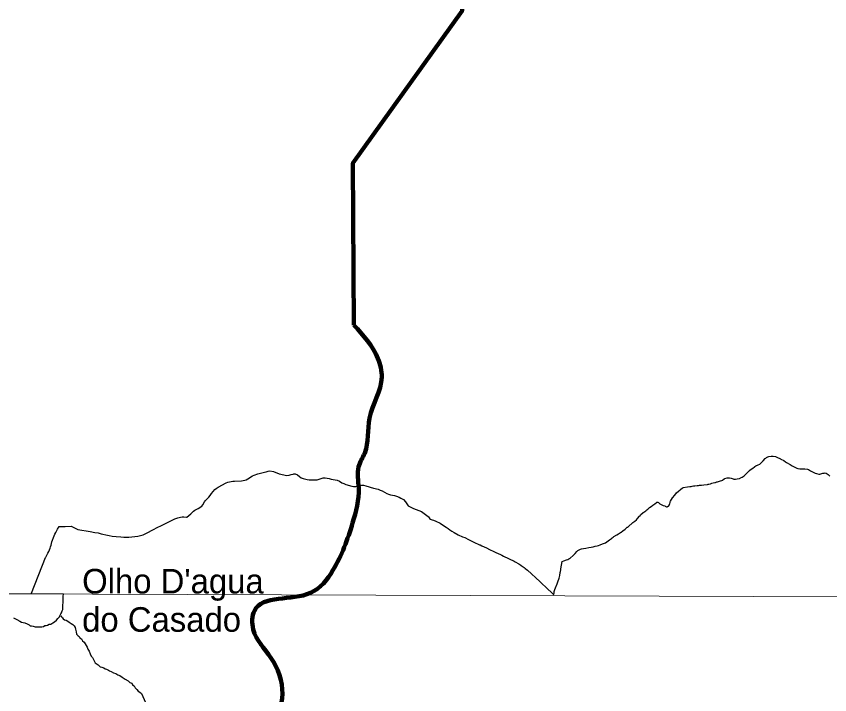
# Model space of a CAD drawing. Extents: x 553962 to 842807, y 8883888 to 9032388.
# Drawn here: x 628002 to 644560, y 8947589 to 8961392 of the extents above; entities that cross this region are included whole.
import ezdxf

# ---------------------------------------------------------------- set-up
doc = ezdxf.new("R2010")
doc.units = 0
doc.header["$LTSCALE"] = 200
for name, color, linetype, lineweight in [('1', 7, 'Continuous', 13), ('12', 7, 'Continuous', 25), ('21', 7, 'Continuous', 25), ('9', 7, 'Continuous', 90)]:
    doc.layers.add(name, color=color, linetype=linetype, lineweight=lineweight)
doc.layers.add('41', color=7, linetype='Continuous')

msp = doc.modelspace()

# ---------------------------------------------------------------- linework, layer by layer
at = {"layer": '1'}
msp.add_line((565315.3, 8949866.8), (791497.7, 8949052.2), dxfattribs=at)
at = {"layer": '12'}
for points in [[(642470.5, 8951998.4), (642488.5, 8952001.9), (642522.6, 8951999.2), (642556.7, 8951992.9), (642592.3, 8951983), (642609.4, 8951976.9), (642626.5, 8951976.6), (642642.7, 8951974.7), (642676.8, 8951977.7), (642721, 8951987.2), (642724.8, 8951990.9), (642735.1, 8951994.5), (642743.5, 8952000), (642776.2, 8952012.3), (642776.2, 8952012.3), (642820.9, 8952041.1), (642834.6, 8952053), (642890.7, 8952119.2), (642906.7, 8952133.2), (642928.9, 8952148.8), (642967.9, 8952182.8), (642985, 8952193.5), (643037.1, 8952235.1), (643053.7, 8952245), (643102.2, 8952265.8), (643135, 8952282.2), (643159.6, 8952300.8), (643178.3, 8952317.8), (643202.9, 8952349.8), (643246, 8952395.7), (643257.2, 8952401.9), (643271.1, 8952413.3), (643302.7, 8952429.5), (643320.6, 8952432.8), (643369.3, 8952438.9), (643405.8, 8952441), (643454.6, 8952432.6), (643499.9, 8952415)], [(643499.9, 8952415), (643545.2, 8952397.3), (643559.2, 8952390.7), (643566.2, 8952384), (643622.9, 8952353.1), (643662.1, 8952326.2), (643681.9, 8952316.1), (643757.2, 8952271.2), (643777.1, 8952261.1), (643797.8, 8952247.5), (643838.2, 8952227.2), (643875.4, 8952204.5), (643892.2, 8952196.2), (643909.7, 8952190.3), (643950.5, 8952184.5), (644032, 8952186.5), (644053.2, 8952185.5), (644110.7, 8952177), (644118, 8952173), (644124.4, 8952171.9), (644149.9, 8952156.7), (644169.2, 8952143), (644206.8, 8952123.1), (644263.5, 8952096.7), (644288, 8952088.8), (644341, 8952079.2), (644360.9, 8952079), (644380.1, 8952081.2), (644401.4, 8952086.5), (644422.7, 8952094.8), (644444, 8952099.1), (644465.3, 8952100.1), (644485.8, 8952097), (644525.6, 8952067.7), (644562.3, 8952035.3)], [(631977.1, 8951685.3), (632043.8, 8951765.5), (632068.1, 8951787.6), (632108.7, 8951813.7), (632273.3, 8951897.1), (632308.2, 8951910.2), (632340.4, 8951920.2), (632377.3, 8951927.3), (632410.5, 8951931.4), (632445.5, 8951933.4), (632583, 8951943.7), (632651.1, 8951951.8), (632683.3, 8951961.8), (632714.5, 8951977.9), (632813.6, 8952039.2), (632846.3, 8952056.3), (632917.7, 8952084.4), (633052.1, 8952118.7), (633089.1, 8952126.8), (633126.8, 8952136.8), (633162.7, 8952142.2)], [(633162.7, 8952142.2), (633241, 8952131), (633351.4, 8952085.1), (633389.4, 8952073.2), (633476, 8952053.2), (633512.3, 8952049.3), (633554.8, 8952055.4), (633594.5, 8952068.5), (633634.9, 8952078.5), (633648.8, 8952084.6), (633676.3, 8952083.6), (633727.4, 8952060.7), (633770.1, 8952027.7), (633804.1, 8952004.7), (633842.6, 8951989.7), (633923.6, 8951967.8), (633963.1, 8951960.9), (634004.5, 8951957.9), (634043, 8951958), (634125.1, 8951962.1), (634165.6, 8951972.2), (634207, 8951990.3), (634246.6, 8951999.4), (634288, 8952002.5), (634328.5, 8951997.5), (634368.9, 8951987.6), (634409.5, 8951974.6), (634490.4, 8951962.7), (634530.8, 8951952.8), (634579.8, 8951930.8), (634627.9, 8951901.8), (634668.1, 8951883.9), (634709.8, 8951868.9), (634829.3, 8951833.1), (634866.1, 8951824.1)], [(640395.6, 8950959.1), (640439.6, 8950994.5), (640445, 8950997), (640447, 8951000.5), (640457.8, 8951007.8), (640555.3, 8951093.5), (640594.1, 8951120.7), (640626.7, 8951148.9), (640649.6, 8951173.9), (640686.4, 8951218.1), (640699.1, 8951231), (640711, 8951247), (640763.7, 8951297.4), (640775.4, 8951302.8), (640813.7, 8951328.4), (640837.7, 8951348), (640857.9, 8951367.2), (640891.5, 8951395.5), (640923.9, 8951418.5), (640957.6, 8951446.5), (641002, 8951475.6), (641024.2, 8951496.1), (641040.4, 8951506.2), (641048.4, 8951506.8), (641063.8, 8951505.7), (641076.1, 8951500.8), (641103, 8951472.9), (641113.2, 8951465), (641125.4, 8951459), (641140.6, 8951455), (641169.7, 8951440.6), (641200.2, 8951430.5), (641213.3, 8951424.4), (641238.7, 8951409.4), (641250.3, 8951409.1), (641257, 8951415.1), (641263.6, 8951416.6), (641271.5, 8951423.5), (641278.8, 8951426.2), (641300.2, 8951451.3), (641301.2, 8951463.4), (641305.1, 8951471.8), (641310.1, 8951499.8), (641314, 8951513.2), (641320.4, 8951528.1), (641359.3, 8951592.4), (641405.6, 8951650.4), (641442.9, 8951693.2), (641484.3, 8951731.3), (641515.2, 8951757.2), (641526.5, 8951768.3), (641559, 8951794.4), (641579.3, 8951807.2), (641667.6, 8951821), (641713.1, 8951823.5), (641738.9, 8951828.1), (641757.8, 8951829.8), (641786.9, 8951836), (641814.4, 8951840), (641860.7, 8951842.5), (641877.2, 8951846.8), (641891.3, 8951848.7), (641906.2, 8951849), (641921.9, 8951853), (641936.1, 8951853.2), (641951.8, 8951855.2), (641995, 8951856.3), (642070.3, 8951868.1), (642085.2, 8951872.2), (642100.9, 8951874.6), (642130, 8951881.9), (642144.9, 8951887.1), (642160.5, 8951889.6), (642189.7, 8951897.8), (642218.7, 8951904.1), (642234.4, 8951909.5), (642263.5, 8951916.8), (642278.1, 8951923.3), (642336.6, 8951938.4), (642365, 8951949.3), (642376.5, 8951955.1), (642413.4, 8951978.7), (642427.4, 8951986.2), (642470.5, 8951998.4)], [(634866.1, 8951824.1), (634873.4, 8951824.1), (634910.2, 8951826.2), (634950.7, 8951837.2), (634989.1, 8951847.3), (635028.1, 8951852.4), (635071.3, 8951849.5), (635114.6, 8951840.5), (635272.6, 8951793.7), (635367.2, 8951768.8), (635408.9, 8951751.8), (635451.4, 8951736.9), (635498.6, 8951712.9), (635544.2, 8951684), (635579.4, 8951666), (635619.9, 8951654), (635700.8, 8951640.1), (635740.5, 8951628.2), (635792.4, 8951609.2), (635828.7, 8951590.2), (635872.5, 8951570.3), (635883.6, 8951562.3), (635922.4, 8951513.3), (635950.1, 8951475.3), (635979.6, 8951429.2), (636087.1, 8951379.3), (636253.1, 8951319.5), (636386.5, 8951215.6), (636391.7, 8951209.6), (636419.7, 8951164.5), (636421.7, 8951160.5), (636421.7, 8951160.5), (636421.7, 8951160.5)], [(628309.2, 8949653.4), (628599.7, 8950377.9), (628601.3, 8950384.9), (628641.4, 8950470.1), (628663, 8950503.2), (628681.3, 8950538.3), (628691.8, 8950567.4), (628700.4, 8950599.4), (628711, 8950631.5), (628727.3, 8950696.6), (628774.6, 8950822.9), (628788.9, 8950856), (628806.9, 8950888.1), (628840.8, 8950956.2), (628872.2, 8951013.3), (628996.9, 8951009.5), (629121.2, 8951016.8), (629253.8, 8950950.8), (629505.9, 8950912.2), (629601.8, 8950889.3), (629665.7, 8950879.4), (629728.8, 8950861.5), (629762.5, 8950857.5), (629825.6, 8950843.6), (629857.5, 8950834.6), (629889.5, 8950829.7), (629956.5, 8950815.8), (630035.3, 8950806.9), (630130.2, 8950799), (630192.3, 8950791.1), (630294.1, 8950795.2), (630475.3, 8950814.6), (630582.1, 8950842.8), (630610.8, 8950852.8), (630639.6, 8950867.9), (630696.5, 8950894.1), (630755.1, 8950927.2), (630784, 8950940.3), (630880.8, 8950995.5), (630942.3, 8951026.6), (631001.9, 8951051.8), (631119.9, 8951113.1), (631172.4, 8951142.2), (631232.1, 8951169.3), (631292.6, 8951189.5), (631346.6, 8951202.6), (631380.4, 8951208.6), (631413.7, 8951209.7), (631469.4, 8951200.8), (631474.6, 8951200.8), (631553, 8951268), (631581, 8951297.1), (631608.2, 8951320.2), (631637.5, 8951342.2), (631707.2, 8951377.4), (631776.4, 8951422.6), (631796.8, 8951451.7), (631836.1, 8951514.8), (631854.5, 8951538.9), (631890.1, 8951573), (631921.4, 8951606.1), (631949.1, 8951643.2), (631977.1, 8951685.3), (631977.1, 8951685.3)], [(636421.7, 8951160.5), (636492.6, 8951137.6), (636543.8, 8951117.6), (636626.9, 8951075.7), (636719.5, 8951017.8), (636751.5, 8950995.8), (636795.3, 8950967.8), (636826.1, 8950942.8), (636870.7, 8950918.8), (636915.4, 8950886.9), (636996.5, 8950842.9), (637085.1, 8950803), (637131.6, 8950784.1), (637204.7, 8950745.1)], [(639116.2, 8950297.4), (639149.8, 8950312.8), (639201.4, 8950330), (639225.8, 8950341.2), (639251, 8950352), (639254.3, 8950354.5), (639265.5, 8950361.8), (639275.1, 8950369.6), (639340.1, 8950423.9), (639377.5, 8950461.2), (639409.6, 8950499.5), (639433.2, 8950522.9), (639488.6, 8950549.3), (639509.1, 8950557.4), (639550.9, 8950566.9), (639593.5, 8950572.4), (639658.3, 8950586.3), (639703.6, 8950591.1), (639744.3, 8950599.4), (639786.9, 8950612), (639828.7, 8950619.4), (639850, 8950624.7), (639890, 8950637.6), (639937.9, 8950655.7), (639994.2, 8950681.9), (640048.1, 8950716.4), (640078.5, 8950742.4), (640115.7, 8950767), (640133.5, 8950781.2), (640151.5, 8950793.1), (640167.6, 8950806.8), (640226.6, 8950841.8), (640263.4, 8950861.3), (640263.4, 8950861.3), (640280.4, 8950873), (640297.6, 8950886.7), (640316.3, 8950898), (640351.7, 8950923.7), (640395.6, 8950959.1)], [(637204.7, 8950745.1), (637236.4, 8950731.9), (637342.1, 8950681.2), (637402.5, 8950654.2), (637429.5, 8950639.7), (637442.2, 8950635.2), (637481.3, 8950617.9), (637571.5, 8950575), (637632.7, 8950543.3), (637724.2, 8950501.8), (637761.9, 8950483), (637855.8, 8950440.2), (637882.2, 8950429.6), (637917.4, 8950409.5), (638134, 8950306.5), (638157.9, 8950291.9), (638228.5, 8950253.9), (638272.8, 8950224.6), (638304.2, 8950197.7), (638316.9, 8950191.8), (638323.7, 8950184.3), (638335.4, 8950179.9), (638341.5, 8950174.2), (638346.7, 8950171.6), (638352.3, 8950164.8), (638359.3, 8950163), (638363.3, 8950157.6), (638382.1, 8950140), (638404.6, 8950123.8), (638657.4, 8949892.2), (638716.1, 8949835.5), (638775.8, 8949782.1), (638818.1, 8949741), (638898.3, 8949671.3), (638932.1, 8949635.9), (638944.8, 8949626.3), (638949.6, 8949652.2), (638952.9, 8949690.6), (638957.5, 8949711.3), (638963.7, 8949729.7), (638981, 8949766.6), (639010.6, 8949844.8), (639027.5, 8949883.2), (639052, 8949959.9), (639066.5, 8950015.8), (639075.2, 8950073.3), (639081, 8950095.8), (639085, 8950131.7), (639085.5, 8950153.3), (639116.2, 8950297.4)], [(628906.4, 8949193.4), (628921.3, 8949173.3), (628943.6, 8949150.6), (628956, 8949130.5), (628983.3, 8949110.3), (629015.8, 8949102.6), (629048.2, 8949084.8), (629080.5, 8949064.6), (629117.8, 8949036.8), (629155.2, 8949016.5), (629177.5, 8948991.3), (629197.3, 8948958.7), (629204.5, 8948921.1), (629221.6, 8948865.9), (629226.2, 8948820.8), (629261, 8948788), (629283.4, 8948770.3), (629298.2, 8948742.7), (629330.6, 8948725), (629352.8, 8948687.2), (629385, 8948654.5), (629404.8, 8948624.3), (629422.1, 8948591.7), (629441.8, 8948556.5), (629459, 8948516.3), (629488.7, 8948473.6), (629503.3, 8948423.4), (629522.9, 8948370.7), (629552.7, 8948342.9), (629572.5, 8948307.8), (629604.5, 8948240), (629669.2, 8948197)], [(629669.2, 8948197), (629708.9, 8948159.2), (629743.8, 8948146.4), (629783.8, 8948136.1), (629808.6, 8948118.4), (629841.1, 8948105.7), (629875.9, 8948088), (629898.4, 8948077.8), (629935.8, 8948062.5), (629978.1, 8948034.7), (630025.5, 8948021.9), (630067.8, 8947994.1), (630107.7, 8947976.3), (630157.5, 8947945.9), (630219.7, 8947905.4), (630282, 8947872.5), (630311.8, 8947839.7), (630351.7, 8947824.4), (630368.9, 8947791.8), (630401.2, 8947769), (630421, 8947728.8), (630455.7, 8947696.1), (630480.5, 8947660.8), (630515.3, 8947640.6), (630547.6, 8947610.3), (630810.8, 8947030.3)]]:
    msp.add_lwpolyline(points, dxfattribs=at)
at = {"layer": '21'}
msp.add_lwpolyline([(627948.7, 8949152.7), (628014.1, 8949120.8), (628075.7, 8949086.9), (628110.6, 8949066.7), (628173, 8949048.9), (628225.4, 8949033.6), (628265.2, 8949010.9), (628287.6, 8948988.2), (628315.1, 8948988.1), (628342.5, 8948985.4), (628384.9, 8948970.2), (628409.9, 8948970.1), (628442.4, 8948969.9), (628474.9, 8948969.7), (628499.9, 8948969.6), (628525, 8948972), (628555, 8948976.8), (628582.6, 8948994.2), (628612.6, 8948994), (628640.2, 8949006.4), (628670.3, 8949021.2), (628702.8, 8949023.6), (628745.5, 8949053.4), (628778.1, 8949073.2), (628818.4, 8949105.5), (628848.6, 8949140.4), (628878.8, 8949175.3), (628896.5, 8949205.2), (628909.2, 8949232.7), (628924.4, 8949257.6), (628937.2, 8949297.6), (628949.8, 8949325), (628950, 8949352.6), (628950.3, 8949387.6), (628952.9, 8949412.6), (628953.3, 8949462.7), (628953.4, 8949482.7), (628953.7, 8949520.2), (628953.8, 8949540.2), (628954, 8949562.7), (628954.2, 8949595.3), (628960.2, 8949636.4), (627600.1, 8949642.9)], dxfattribs=at)
at = {"layer": '9'}
msp.add_lwpolyline([(637260.6, 8972975.8), (637076.8, 8961505.7), (634855.7, 8958401.3), (634875.3, 8955110.3)], dxfattribs=at)
for points in [[(637260.6, 8972975.8), (641524.5, 8971056.2), (652526.1, 8965412.7), (653164.3, 8965062.8), (670790.5, 8953770.1), (686194, 8943929.9), (696283.3, 8937647.1)], [(630387.4, 8939797.8), (630434.2, 8940142.1), (630686.5, 8940523.6), (631192.1, 8941084.2), (631927.5, 8941519.8), (632256.1, 8941901.8), (632534.2, 8942207.6), (633141.9, 8942718.3), (633623.2, 8943101.4), (634002.9, 8943433.2), (634103.5, 8943636.5), (634126.4, 8944067), (633968.9, 8944876), (633685.2, 8945506.9), (633295.3, 8946896.6), (633418.3, 8947606.3), (633184.9, 8948338.8), (632825.2, 8948918.6), (632848.4, 8949298.5), (633991.4, 8949661), (634446.8, 8950119.9), (634848.2, 8951084.8), (634971.3, 8951794.5), (634968.7, 8952224.9), (635094.3, 8952504.3), (635191.9, 8953213.8), (635441.4, 8954051.1), (635362.8, 8954430.2), (634875.3, 8955110.3)]]:
    msp.add_spline(points, degree=3, dxfattribs=at)

# ---------------------------------------------------------------- texts
at = {"layer": '41'}
for s, p in [("Olho D'agua", (629342.2, 8949648.8)), ('do Casado', (629342.2, 8948869.8))]:
    msp.add_text(s, height=500, dxfattribs=at).set_placement(p)

doc.saveas('drawing.dxf')
